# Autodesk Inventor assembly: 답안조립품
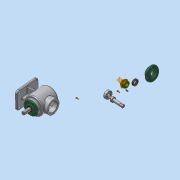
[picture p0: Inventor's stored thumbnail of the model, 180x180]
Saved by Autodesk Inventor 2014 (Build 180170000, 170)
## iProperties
Created: 2016-09
Part Number: 답안조립품
Document SubType Name: Assembly
Designer: 402-003
Author: 402-003
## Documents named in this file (14)
- C:\Users\402-003\Desktop\460907V1009\답안조립품.iam
- C:\Users\402-003\Desktop\460907V1009\본체.ipt
- C:\Users\402-003\Desktop\460907V1009\M4.ipt
- C:\Users\402-003\Desktop\460907V1009\메인 베벨기어.ipt
- C:\Users\402-003\Desktop\460907V1009\메인 축.ipt
- 메인 축.ipt
- C:\Users\402-003\Desktop\460907V1009\베어링 6203.ipt
- C:\Users\402-003\Desktop\460907V1009\서브 베벨기어.ipt
- C:\Users\402-003\Desktop\460907V1009\서브 축.ipt
- 서브 축.ipt
- C:\Users\402-003\Desktop\460907V1009\오일실 17 32 8.ipt
- C:\Users\402-003\Desktop\460907V1009\커버.ipt
- C:\Users\402-003\Desktop\460907V1009\키 4x4.ipt
- C:\Users\402-003\Desktop\460907V1009\키 5x5.ipt
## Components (2 placed, 1 different names)
1. M4:1
2. M4:2
